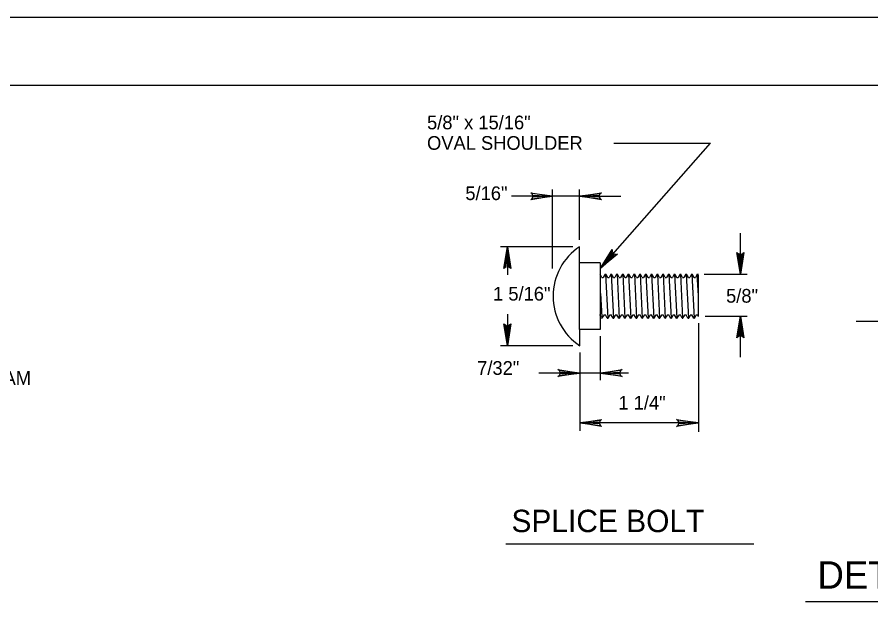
# Model space of a CAD drawing. Extents: x 637628 to 640188, y 298266 to 300751.
# Drawn here: x 638647.9 to 638834.9, y 299324.4 to 299453.6 of the extents above; entities that cross this region are included whole.
import ezdxf

# ---------------------------------------------------------------- set-up
doc = ezdxf.new("R2010")
doc.units = 0
for name, color, linetype in [('1', 7, 'Continuous'), ('2', 7, 'Continuous'), ('3', 7, 'Continuous'), ('PLT-BNDY', 7, 'Continuous')]:
    doc.layers.add(name, color=color, linetype=linetype)

msp = doc.modelspace()

# ---------------------------------------------------------------- linework, layer by layer
at = {"layer": '1'}
msp.add_line((638831.66, 299386.95), (638974.38, 299386.95), dxfattribs=at)
msp.add_lwpolyline([(639104.52, 298874.58), (639104.52, 299438.58), (638318.52, 299438.58), (638318.52, 298874.58), (639104.52, 298874.58), (639104.52, 298900.93), (638904.52, 298900.93), (638904.52, 298965.61), (639104.52, 298965.61), (639104.52, 298994.58), (638904.52, 298994.58), (638904.52, 298874.58), (638983.33, 298874.58), (638983.33, 298900.93), (638983.33, 298874.58), (639060.33, 298874.58), (639060.33, 298900.93), (639060.33, 298888.62), (639104.52, 298888.62)], dxfattribs=at)
at = {"layer": '2'}
for p, q in [((638775.64, 299398.55), (638799.75, 299425.96)), ((638778.55, 299425.96), (638799.75, 299425.96)), ((638765.14, 299398.52), (638765.14, 299415.84)), ((638771.08, 299404.78), (638771.08, 299415.84)), ((638771.08, 299414.34), (638756.14, 299414.34)), ((638771.08, 299414.34), (638780.08, 299414.34)), ((638806.3, 299397.24), (638806.3, 299406.24)), ((638769.58, 299403.28), (638753.76, 299403.28)), ((638755.26, 299403.28), (638755.26, 299397.11)), ((638771.08, 299385.16), (638771.08, 299403.28)), ((638775.6, 299399.73), (638771.08, 299399.73)), ((638775.6, 299399.73), (638775.6, 299385.16)), ((638775.97, 299396.56), (638775.56, 299397.24)), ((638776.67, 299397.24), (638776.26, 299396.56)), ((638776.67, 299397.24), (638776.83, 299397.24)), ((638777.23, 299396.56), (638776.83, 299397.24)), ((638777.3, 299387.66), (638776.83, 299397.24)), ((638777.93, 299397.24), (638777.52, 299396.56)), ((638777.93, 299397.24), (638778.09, 299397.24)), ((638778.49, 299396.56), (638778.09, 299397.24)), ((638778.56, 299387.66), (638778.09, 299397.24)), ((638779.19, 299397.24), (638778.79, 299396.56)), ((638779.19, 299397.24), (638779.35, 299397.24)), ((638779.75, 299396.56), (638779.35, 299397.24)), ((638779.82, 299387.66), (638779.35, 299397.24)), ((638780.45, 299397.24), (638780.05, 299396.56)), ((638780.45, 299397.24), (638780.61, 299397.24)), ((638781.02, 299396.56), (638780.61, 299397.24)), ((638781.09, 299387.66), (638780.61, 299397.24)), ((638781.71, 299397.24), (638781.31, 299396.56)), ((638781.71, 299397.24), (638781.87, 299397.24)), ((638782.28, 299396.56), (638781.87, 299397.24)), ((638782.35, 299387.66), (638781.87, 299397.24)), ((638782.98, 299397.24), (638782.57, 299396.56)), ((638782.98, 299397.24), (638783.14, 299397.24)), ((638783.54, 299396.56), (638783.14, 299397.24)), ((638783.61, 299387.66), (638783.14, 299397.24)), ((638784.24, 299397.24), (638783.83, 299396.56)), ((638784.24, 299397.24), (638784.4, 299397.24)), ((638784.8, 299396.56), (638784.4, 299397.24)), ((638784.87, 299387.66), (638784.4, 299397.24)), ((638785.5, 299397.24), (638785.1, 299396.56)), ((638785.5, 299397.24), (638785.66, 299397.24)), ((638786.06, 299396.56), (638785.66, 299397.24)), ((638786.13, 299387.66), (638785.66, 299397.24)), ((638786.76, 299397.24), (638786.36, 299396.56)), ((638786.76, 299397.24), (638786.92, 299397.24)), ((638787.33, 299396.56), (638786.92, 299397.24)), ((638787.39, 299387.66), (638786.92, 299397.24)), ((638788.03, 299397.24), (638787.62, 299396.56)), ((638788.03, 299397.24), (638788.18, 299397.24)), ((638788.59, 299396.56), (638788.18, 299397.24)), ((638788.66, 299387.66), (638788.18, 299397.24)), ((638789.29, 299397.24), (638788.88, 299396.56)), ((638789.29, 299397.24), (638789.44, 299397.24)), ((638789.85, 299396.56), (638789.44, 299397.24)), ((638789.92, 299387.66), (638789.44, 299397.24)), ((638790.55, 299397.24), (638790.14, 299396.56)), ((638790.55, 299397.24), (638790.71, 299397.24)), ((638791.11, 299396.56), (638790.71, 299397.24)), ((638791.18, 299387.66), (638790.71, 299397.24)), ((638791.81, 299397.24), (638791.41, 299396.56)), ((638791.81, 299397.24), (638791.97, 299397.24)), ((638792.38, 299396.56), (638791.97, 299397.24)), ((638792.44, 299387.66), (638791.97, 299397.24)), ((638793.07, 299397.24), (638792.67, 299396.56)), ((638793.07, 299397.24), (638793.23, 299397.24)), ((638793.64, 299396.56), (638793.23, 299397.24)), ((638793.7, 299387.66), (638793.23, 299397.24)), ((638794.34, 299397.24), (638793.93, 299396.56)), ((638794.34, 299397.24), (638794.49, 299397.24)), ((638794.9, 299396.56), (638794.49, 299397.24)), ((638794.97, 299387.66), (638794.49, 299397.24)), ((638795.6, 299397.24), (638795.19, 299396.56)), ((638795.6, 299397.24), (638795.75, 299397.24)), ((638796.16, 299396.56), (638795.75, 299397.24)), ((638796.23, 299387.66), (638795.75, 299397.24)), ((638796.86, 299397.24), (638796.45, 299396.56)), ((638796.86, 299397.24), (638797.02, 299397.24)), ((638797.09, 299392.53), (638796.86, 299397.24)), ((638797.09, 299397.11), (638797.02, 299397.24)), ((638797.13, 299388.02), (638797.13, 299397.08)), ((638798.36, 299397.24), (638807.8, 299397.24)), ((638776.01, 299387.94), (638775.72, 299393.03)), ((638755.26, 299388.53), (638755.26, 299381.6)), ((638775.88, 299387.66), (638775.48, 299388.34)), ((638776.26, 299388.04), (638776.04, 299387.66)), ((638776.44, 299388.34), (638776.26, 299388.04)), ((638777.14, 299387.66), (638776.74, 299388.34)), ((638777.52, 299388.04), (638777.3, 299387.66)), ((638777.7, 299388.34), (638777.52, 299388.04)), ((638778.4, 299387.66), (638778, 299388.34)), ((638778.79, 299388.04), (638778.56, 299387.66)), ((638778.97, 299388.34), (638778.79, 299388.04)), ((638779.66, 299387.66), (638779.26, 299388.34)), ((638780.05, 299388.04), (638779.82, 299387.66)), ((638780.23, 299388.34), (638780.05, 299388.04)), ((638780.93, 299387.66), (638780.52, 299388.34)), ((638781.31, 299388.04), (638781.09, 299387.66)), ((638781.49, 299388.34), (638781.31, 299388.04)), ((638782.19, 299387.66), (638781.78, 299388.34)), ((638782.57, 299388.04), (638782.35, 299387.66)), ((638782.75, 299388.34), (638782.57, 299388.04)), ((638783.45, 299387.66), (638783.05, 299388.34)), ((638783.83, 299388.04), (638783.61, 299387.66)), ((638784.01, 299388.34), (638783.83, 299388.04)), ((638784.71, 299387.66), (638784.31, 299388.34)), ((638785.1, 299388.04), (638784.87, 299387.66)), ((638785.28, 299388.34), (638785.1, 299388.04)), ((638785.98, 299387.66), (638785.57, 299388.34)), ((638786.36, 299388.04), (638786.13, 299387.66)), ((638786.54, 299388.34), (638786.36, 299388.04)), ((638787.24, 299387.66), (638786.83, 299388.34)), ((638787.62, 299388.04), (638787.39, 299387.66)), ((638787.8, 299388.34), (638787.62, 299388.04)), ((638788.5, 299387.66), (638788.09, 299388.34)), ((638788.88, 299388.04), (638788.66, 299387.66)), ((638789.06, 299388.34), (638788.88, 299388.04)), ((638789.76, 299387.66), (638789.36, 299388.34)), ((638790.14, 299388.04), (638789.92, 299387.66)), ((638790.33, 299388.34), (638790.14, 299388.04)), ((638791.02, 299387.66), (638790.62, 299388.34)), ((638791.41, 299388.04), (638791.18, 299387.66)), ((638791.59, 299388.34), (638791.41, 299388.04)), ((638792.29, 299387.66), (638791.88, 299388.34)), ((638792.67, 299388.04), (638792.44, 299387.66)), ((638792.85, 299388.34), (638792.67, 299388.04)), ((638793.55, 299387.66), (638793.14, 299388.34)), ((638793.93, 299388.04), (638793.7, 299387.66)), ((638794.11, 299388.34), (638793.93, 299388.04)), ((638794.81, 299387.66), (638794.4, 299388.34)), ((638795.19, 299388.04), (638794.97, 299387.66)), ((638795.37, 299388.34), (638795.19, 299388.04)), ((638796.07, 299387.66), (638795.67, 299388.34)), ((638796.45, 299388.04), (638796.23, 299387.66)), ((638796.64, 299388.34), (638796.45, 299388.04)), ((638797.09, 299388.06), (638796.93, 299388.34)), ((638798.59, 299388.06), (638807.8, 299388.06)), ((638806.3, 299379.06), (638806.3, 299388.06)), ((638775.6, 299385.16), (638771.08, 299385.16)), ((638771.11, 299381.6), (638771.11, 299385.16)), ((638797.09, 299386.56), (638797.09, 299362.71)), ((638775.6, 299383.66), (638775.6, 299374.05)), ((638769.61, 299381.6), (638753.76, 299381.6)), ((638771.11, 299380.1), (638771.11, 299362.97)), ((638771.11, 299376.75), (638771.11, 299374.1)), ((638775.6, 299375.6), (638762.11, 299375.6)), ((638781.77, 299375.6), (638775.6, 299375.6)), ((638797.09, 299364.69), (638771.11, 299364.69)), ((638754.91, 299338.19), (638809.22, 299338.19))]:
    msp.add_line(p, q, dxfattribs=at)
for points in [[(638760.6, 299414.91), (638760.77, 299414.58), (638765.14, 299414.34), (638760.6, 299414.91), (638760.37, 299415.11), (638765.14, 299414.34), (638760.77, 299414.13), (638760.61, 299413.8), (638765.14, 299414.34), (638760.37, 299413.58), (638760.61, 299413.8)], [(638775.62, 299413.77), (638775.45, 299414.1), (638771.08, 299414.34), (638775.62, 299413.77), (638775.85, 299413.57), (638771.08, 299414.34), (638775.45, 299414.56), (638775.61, 299414.88), (638771.08, 299414.34), (638775.85, 299415.1), (638775.61, 299414.88)], [(638754.69, 299398.74), (638755.02, 299398.91), (638755.26, 299403.28), (638754.69, 299398.74), (638754.49, 299398.51), (638755.26, 299403.28), (638755.48, 299398.91), (638755.8, 299398.75), (638755.26, 299403.28), (638756.02, 299398.51), (638755.8, 299398.75)], [(638779.07, 299401.58), (638778.71, 299401.67), (638775.64, 299398.55), (638779.07, 299401.58), (638779.38, 299401.63), (638775.64, 299398.55), (638778.37, 299401.97), (638778.23, 299402.31), (638775.64, 299398.55), (638778.23, 299402.63), (638778.23, 299402.31)], [(638806.87, 299401.78), (638806.54, 299401.61), (638806.3, 299397.24), (638806.87, 299401.78), (638807.07, 299402.01), (638806.3, 299397.24), (638806.08, 299401.61), (638805.76, 299401.77), (638806.3, 299397.24), (638805.54, 299402.01), (638805.76, 299401.77)], [(638775.97, 299396.56), (638776.26, 299396.56)], [(638777.23, 299396.56), (638777.52, 299396.56)], [(638778.49, 299396.56), (638778.79, 299396.56)], [(638779.75, 299396.56), (638780.05, 299396.56)], [(638781.02, 299396.56), (638781.31, 299396.56)], [(638782.28, 299396.56), (638782.57, 299396.56)], [(638783.54, 299396.56), (638783.83, 299396.56)], [(638784.8, 299396.56), (638785.1, 299396.56)], [(638786.06, 299396.56), (638786.36, 299396.56)], [(638787.33, 299396.56), (638787.62, 299396.56)], [(638788.59, 299396.56), (638788.88, 299396.56)], [(638789.85, 299396.56), (638790.14, 299396.56)], [(638791.11, 299396.56), (638791.41, 299396.56)], [(638792.38, 299396.56), (638792.67, 299396.56)], [(638793.64, 299396.56), (638793.93, 299396.56)], [(638794.9, 299396.56), (638795.19, 299396.56)], [(638796.16, 299396.56), (638796.45, 299396.56)], [(638775.88, 299387.66), (638776.04, 299387.66)], [(638776.44, 299388.34), (638776.74, 299388.34)], [(638777.14, 299387.66), (638777.3, 299387.66)], [(638777.7, 299388.34), (638778, 299388.34)], [(638778.4, 299387.66), (638778.56, 299387.66)], [(638778.97, 299388.34), (638779.26, 299388.34)], [(638779.66, 299387.66), (638779.82, 299387.66)], [(638780.23, 299388.34), (638780.52, 299388.34)], [(638780.93, 299387.66), (638781.09, 299387.66)], [(638781.49, 299388.34), (638781.78, 299388.34)], [(638782.19, 299387.66), (638782.35, 299387.66)], [(638782.75, 299388.34), (638783.04, 299388.34)], [(638783.45, 299387.66), (638783.61, 299387.66)], [(638784.01, 299388.34), (638784.31, 299388.34)], [(638784.71, 299387.66), (638784.87, 299387.66)], [(638785.28, 299388.34), (638785.57, 299388.34)], [(638785.98, 299387.66), (638786.13, 299387.66)], [(638786.54, 299388.34), (638786.83, 299388.34)], [(638787.24, 299387.66), (638787.39, 299387.66)], [(638787.8, 299388.34), (638788.09, 299388.34)], [(638788.5, 299387.66), (638788.66, 299387.66)], [(638789.06, 299388.34), (638789.35, 299388.34)], [(638789.76, 299387.66), (638789.92, 299387.66)], [(638790.33, 299388.34), (638790.62, 299388.34)], [(638791.02, 299387.66), (638791.18, 299387.66)], [(638791.59, 299388.34), (638791.88, 299388.34)], [(638792.29, 299387.66), (638792.44, 299387.66)], [(638792.85, 299388.34), (638793.14, 299388.34)], [(638793.55, 299387.66), (638793.7, 299387.66)], [(638794.11, 299388.34), (638794.4, 299388.34)], [(638794.81, 299387.66), (638794.97, 299387.66)], [(638795.37, 299388.34), (638795.66, 299388.34)], [(638796.07, 299387.66), (638796.23, 299387.66)], [(638796.64, 299388.34), (638796.93, 299388.34)], [(638805.73, 299383.52), (638806.06, 299383.69), (638806.3, 299388.06), (638805.73, 299383.52), (638805.53, 299383.29), (638806.3, 299388.06), (638806.51, 299383.7), (638806.84, 299383.54), (638806.3, 299388.06), (638807.06, 299383.29), (638806.84, 299383.54)], [(638755.83, 299386.14), (638755.5, 299385.97), (638755.26, 299381.6), (638755.83, 299386.14), (638756.03, 299386.37), (638755.26, 299381.6), (638755.04, 299385.97), (638754.72, 299386.13), (638755.26, 299381.6), (638754.5, 299386.37), (638754.72, 299386.13)], [(638766.57, 299376.17), (638766.74, 299375.84), (638771.11, 299375.6), (638766.57, 299376.17), (638766.34, 299376.37), (638771.11, 299375.6), (638766.74, 299375.38), (638766.58, 299375.05), (638771.11, 299375.6), (638766.34, 299374.84), (638766.58, 299375.05)], [(638780.14, 299375.03), (638779.98, 299375.35), (638775.6, 299375.6), (638780.14, 299375.03), (638780.38, 299374.83), (638775.6, 299375.6), (638779.97, 299375.81), (638780.13, 299376.14), (638775.6, 299375.6), (638780.38, 299376.35), (638780.13, 299376.14)], [(638775.65, 299364.12), (638775.48, 299364.45), (638771.11, 299364.69), (638775.65, 299364.12), (638775.88, 299363.92), (638771.11, 299364.69), (638775.48, 299364.91), (638775.64, 299365.23), (638771.11, 299364.69), (638775.88, 299365.45), (638775.64, 299365.23)], [(638792.55, 299365.26), (638792.72, 299364.93), (638797.09, 299364.69), (638792.55, 299365.26), (638792.32, 299365.46), (638797.09, 299364.69), (638792.73, 299364.47), (638792.56, 299364.15), (638797.09, 299364.69), (638792.32, 299363.93), (638792.56, 299364.15)]]:
    msp.add_lwpolyline(points, dxfattribs=at)
msp.add_arc((638778.26, 299392.45), 12.99, 123.5335, 236.6356, dxfattribs=at)
at = {"layer": '3'}
msp.add_line((638820.57, 299325.55), (638871.87, 299325.55), dxfattribs=at)
at = {"layer": 'PLT-BNDY'}
msp.add_lwpolyline([(638278.52, 299453.58), (639119.52, 299453.58), (639119.52, 298859.58), (638278.52, 298859.58)], close=True, dxfattribs=at)

# ---------------------------------------------------------------- texts
at = {"layer": '1'}
for s, p in [('7/32"', (638748.64, 299375.21)), ('12 GAGE W-BEAM', (638616.14, 299373.02)), ('1 1/4"', (638779.58, 299367.59))]:
    msp.add_text(s, height=3, dxfattribs=at).set_placement(p)
at = {"layer": '3'}
for s, height, p in [('5/8" x 15/16"', 3, (638737.66, 299428.99)), ('OVAL SHOULDER', 3, (638737.66, 299424.5)), ('5/16"', 3, (638746.05, 299413.49)), ('1 5/16"', 3, (638752.12, 299391.48)), ('5/8"', 3, (638803.16, 299391.02)), ('SPLICE BOLT', 4.9, (638756.15, 299340.76)), ('DETAIL A', 6, (638823.17, 299328.37))]:
    msp.add_text(s, height=height, dxfattribs=at).set_placement(p)

doc.saveas('drawing.dxf')
